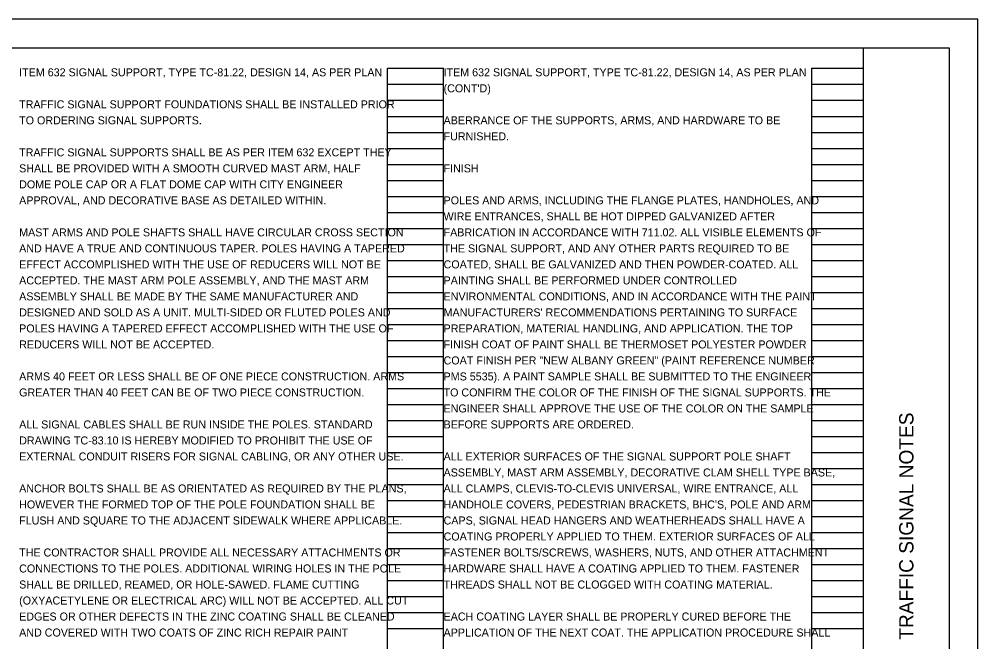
# Model space of a CAD drawing. Extents: x 0 to 34, y 0 to 22.
# Drawn here: x 17.24 to 34, y 11.11 to 22 of the extents above; entities that cross this region are included whole.
import ezdxf

# ---------------------------------------------------------------- set-up
doc = ezdxf.new("R2010")
doc.units = 0
for name, color, linetype in [('SH_Border', 7, 'Continuous'), ('SH_Cut_Line', 7, 'Continuous'), ('SH_Data', 7, 'Continuous'), ('SH_Text', 7, 'Continuous')]:
    doc.layers.add(name, color=color, linetype=linetype)

msp = doc.modelspace()

# ---------------------------------------------------------------- linework, layer by layer
at = {"layer": 'SH_Border'}
msp.add_line((32, 0.5), (32, 21.5), dxfattribs=at)
msp.add_lwpolyline([(1.5, 21.5), (33.5, 21.5), (33.5, 0.5), (1.5, 0.5)], close=True, dxfattribs=at)
at = {"layer": 'SH_Cut_Line'}
msp.add_lwpolyline([(0, 0), (34, 0), (34, 22), (0, 22)], close=True, dxfattribs=at)
at = {"layer": 'SH_Data'}
for p, q in [((23.68, 0.98), (23.68, 21.14)), ((23.68, 21.14), (24.66, 21.14)), ((24.66, 0.98), (24.66, 21.14)), ((31.1, 0.98), (31.1, 21.14)), ((31.1, 21.14), (32, 21.14)), ((32, 0.98), (32, 21.14)), ((23.68, 20.86), (24.66, 20.86)), ((31.1, 20.86), (32, 20.86)), ((23.68, 20.58), (24.66, 20.58)), ((31.1, 20.58), (32, 20.58)), ((23.68, 20.3), (24.66, 20.3)), ((31.1, 20.3), (32, 20.3)), ((23.68, 20.02), (24.66, 20.02)), ((31.1, 20.02), (32, 20.02)), ((23.68, 19.74), (24.66, 19.74)), ((31.1, 19.74), (32, 19.74)), ((23.68, 19.46), (24.66, 19.46)), ((31.1, 19.46), (32, 19.46)), ((23.68, 19.18), (24.66, 19.18)), ((31.1, 19.18), (32, 19.18)), ((23.68, 18.9), (24.66, 18.9)), ((31.1, 18.9), (32, 18.9)), ((23.68, 18.62), (24.66, 18.62)), ((31.1, 18.62), (32, 18.62)), ((23.68, 18.34), (24.66, 18.34)), ((31.1, 18.34), (32, 18.34)), ((23.68, 18.06), (24.66, 18.06)), ((31.1, 18.06), (32, 18.06)), ((23.68, 17.78), (24.66, 17.78)), ((31.1, 17.78), (32, 17.78)), ((23.68, 17.5), (24.66, 17.5)), ((31.1, 17.5), (32, 17.5)), ((23.68, 17.22), (24.66, 17.22)), ((31.1, 17.22), (32, 17.22)), ((23.68, 16.94), (24.66, 16.94)), ((31.1, 16.94), (32, 16.94)), ((23.68, 16.66), (24.66, 16.66)), ((31.1, 16.66), (32, 16.66)), ((23.68, 16.38), (24.66, 16.38)), ((31.1, 16.38), (32, 16.38)), ((23.68, 16.1), (24.66, 16.1)), ((31.1, 16.1), (32, 16.1)), ((23.68, 15.82), (24.66, 15.82)), ((31.1, 15.82), (32, 15.82)), ((23.68, 15.54), (24.66, 15.54)), ((31.1, 15.54), (32, 15.54)), ((23.68, 15.26), (24.66, 15.26)), ((31.1, 15.26), (32, 15.26)), ((23.68, 14.98), (24.66, 14.98)), ((31.1, 14.98), (32, 14.98)), ((23.68, 14.7), (24.66, 14.7)), ((31.1, 14.7), (32, 14.7)), ((23.68, 14.42), (24.66, 14.42)), ((31.1, 14.42), (32, 14.42)), ((23.68, 14.14), (24.66, 14.14)), ((31.1, 14.14), (32, 14.14)), ((23.68, 13.86), (24.66, 13.86)), ((31.1, 13.86), (32, 13.86)), ((23.68, 13.58), (24.66, 13.58)), ((31.1, 13.58), (32, 13.58)), ((23.68, 13.3), (24.66, 13.3)), ((31.1, 13.3), (32, 13.3)), ((23.68, 13.02), (24.66, 13.02)), ((31.1, 13.02), (32, 13.02)), ((23.68, 12.74), (24.66, 12.74)), ((31.1, 12.74), (32, 12.74)), ((23.68, 12.46), (24.66, 12.46)), ((31.1, 12.46), (32, 12.46)), ((23.68, 12.18), (24.66, 12.18)), ((31.1, 12.18), (32, 12.18)), ((23.68, 11.9), (24.66, 11.9)), ((31.1, 11.9), (32, 11.9)), ((23.68, 11.62), (24.66, 11.62)), ((31.1, 11.62), (32, 11.62)), ((23.68, 11.34), (24.66, 11.34)), ((31.1, 11.34), (32, 11.34))]:
    msp.add_line(p, q, dxfattribs=at)

# ---------------------------------------------------------------- texts
msp.add_text('TRAFFIC SIGNAL NOTES', height=0.25, rotation=90, dxfattribs=at).set_placement((32.875, 11.144))
at = {"layer": 'SH_Text'}
for s, p in [('ITEM 632 SIGNAL SUPPORT, TYPE TC-81.22, DESIGN 14, AS PER PLAN', (17.24, 21)), ('ITEM 632 SIGNAL SUPPORT, TYPE TC-81.22, DESIGN 14, AS PER PLAN ', (24.66, 21)), ("(CONT'D)", (24.66, 20.72)), ('TRAFFIC SIGNAL SUPPORT FOUNDATIONS SHALL BE INSTALLED PRIOR ', (17.24, 20.44)), ('TO ORDERING SIGNAL SUPPORTS.', (17.24, 20.16)), ('ABERRANCE OF THE SUPPORTS, ARMS, AND HARDWARE TO BE ', (24.66, 20.16)), ('FURNISHED.', (24.66, 19.88)), ('TRAFFIC SIGNAL SUPPORTS SHALL BE AS PER ITEM 632 EXCEPT THEY ', (17.24, 19.6)), ('SHALL BE PROVIDED WITH A SMOOTH CURVED MAST ARM, HALF ', (17.24, 19.32)), ('FINISH', (24.66, 19.32)), ('DOME POLE CAP OR A FLAT DOME CAP WITH CITY ENGINEER ', (17.24, 19.04)), ('APPROVAL, AND DECORATIVE BASE AS DETAILED WITHIN.', (17.24, 18.76)), ('POLES AND ARMS, INCLUDING THE FLANGE PLATES, HANDHOLES, AND ', (24.66, 18.76)), ('WIRE ENTRANCES, SHALL BE HOT DIPPED GALVANIZED AFTER ', (24.66, 18.48)), ('MAST ARMS AND POLE SHAFTS SHALL HAVE CIRCULAR CROSS SECTION ', (17.24, 18.2)), ('FABRICATION IN ACCORDANCE WITH 711.02. ALL VISIBLE ELEMENTS OF ', (24.66, 18.2)), ('AND HAVE A TRUE AND CONTINUOUS TAPER. POLES HAVING A TAPERED ', (17.24, 17.92)), ('THE SIGNAL SUPPORT, AND ANY OTHER PARTS REQUIRED TO BE ', (24.66, 17.92)), ('EFFECT ACCOMPLISHED WITH THE USE OF REDUCERS WILL NOT BE ', (17.24, 17.64)), ('COATED, SHALL BE GALVANIZED AND THEN POWDER-COATED. ALL ', (24.66, 17.64)), ('ACCEPTED. THE MAST ARM POLE ASSEMBLY, AND THE MAST ARM ', (17.24, 17.36)), ('PAINTING SHALL BE PERFORMED UNDER CONTROLLED ', (24.66, 17.36)), ('ASSEMBLY SHALL BE MADE BY THE SAME MANUFACTURER AND ', (17.24, 17.08)), ('ENVIRONMENTAL CONDITIONS, AND IN ACCORDANCE WITH THE PAINT ', (24.66, 17.08)), ('DESIGNED AND SOLD AS A UNIT. MULTI-SIDED OR FLUTED POLES AND ', (17.24, 16.8)), ("MANUFACTURERS' RECOMMENDATIONS PERTAINING TO SURFACE ", (24.66, 16.8)), ('POLES HAVING A TAPERED EFFECT ACCOMPLISHED WITH THE USE OF ', (17.24, 16.52)), ('PREPARATION, MATERIAL HANDLING, AND APPLICATION. THE TOP ', (24.66, 16.52)), ('REDUCERS WILL NOT BE ACCEPTED.', (17.24, 16.24)), ('FINISH COAT OF PAINT SHALL BE THERMOSET POLYESTER POWDER ', (24.66, 16.24)), ('COAT FINISH PER "NEW ALBANY GREEN" (PAINT REFERENCE NUMBER ', (24.66, 15.96)), ('ARMS 40 FEET OR LESS SHALL BE OF ONE PIECE CONSTRUCTION. ARMS ', (17.24, 15.68)), ('PMS 5535). A PAINT SAMPLE SHALL BE SUBMITTED TO THE ENGINEER ', (24.66, 15.68)), ('GREATER THAN 40 FEET CAN BE OF TWO PIECE CONSTRUCTION.', (17.24, 15.4)), ('TO CONFIRM THE COLOR OF THE FINISH OF THE SIGNAL SUPPORTS. THE ', (24.66, 15.4)), ('ENGINEER SHALL APPROVE THE USE OF THE COLOR ON THE SAMPLE ', (24.66, 15.12)), ('ALL SIGNAL CABLES SHALL BE RUN INSIDE THE POLES. STANDARD ', (17.24, 14.84)), ('BEFORE SUPPORTS ARE ORDERED.', (24.66, 14.84)), ('DRAWING TC-83.10 IS HEREBY MODIFIED TO PROHIBIT THE USE OF ', (17.24, 14.56)), ('EXTERNAL CONDUIT RISERS FOR SIGNAL CABLING, OR ANY OTHER USE.', (17.24, 14.28)), ('ALL EXTERIOR SURFACES OF THE SIGNAL SUPPORT POLE SHAFT ', (24.66, 14.28)), ('ASSEMBLY, MAST ARM ASSEMBLY, DECORATIVE CLAM SHELL TYPE BASE, ', (24.66, 14)), ('ANCHOR BOLTS SHALL BE AS ORIENTATED AS REQUIRED BY THE PLANS, ', (17.24, 13.72)), ('ALL CLAMPS, CLEVIS-TO-CLEVIS UNIVERSAL, WIRE ENTRANCE, ALL ', (24.66, 13.72)), ('HOWEVER THE FORMED TOP OF THE POLE FOUNDATION SHALL BE ', (17.24, 13.44)), ("HANDHOLE COVERS, PEDESTRIAN BRACKETS, BHC'S, POLE AND ARM ", (24.66, 13.44)), ('FLUSH AND SQUARE TO THE ADJACENT SIDEWALK WHERE APPLICABLE.', (17.24, 13.16)), ('CAPS, SIGNAL HEAD HANGERS AND WEATHERHEADS SHALL HAVE A ', (24.66, 13.16)), ('COATING PROPERLY APPLIED TO THEM. EXTERIOR SURFACES OF ALL ', (24.66, 12.88)), ('THE CONTRACTOR SHALL PROVIDE ALL NECESSARY ATTACHMENTS OR ', (17.24, 12.6)), ('FASTENER BOLTS/SCREWS, WASHERS, NUTS, AND OTHER ATTACHMENT ', (24.66, 12.6)), ('CONNECTIONS TO THE POLES. ADDITIONAL WIRING HOLES IN THE POLE ', (17.24, 12.32)), ('HARDWARE SHALL HAVE A COATING APPLIED TO THEM. FASTENER ', (24.66, 12.32)), ('SHALL BE DRILLED, REAMED, OR HOLE-SAWED. FLAME CUTTING ', (17.24, 12.04)), ('THREADS SHALL NOT BE CLOGGED WITH COATING MATERIAL.', (24.66, 12.04)), ('(OXYACETYLENE OR ELECTRICAL ARC) WILL NOT BE ACCEPTED. ALL CUT ', (17.24, 11.76)), ('EDGES OR OTHER DEFECTS IN THE ZINC COATING SHALL BE CLEANED ', (17.24, 11.48)), ('EACH COATING LAYER SHALL BE PROPERLY CURED BEFORE THE ', (24.66, 11.48)), ('AND COVERED WITH TWO COATS OF ZINC RICH REPAIR PAINT ', (17.24, 11.2)), ('APPLICATION OF THE NEXT COAT. THE APPLICATION PROCEDURE SHALL ', (24.66, 11.2))]:
    msp.add_text(s, height=0.14, dxfattribs=at).set_placement(p)

doc.saveas('drawing.dxf')
